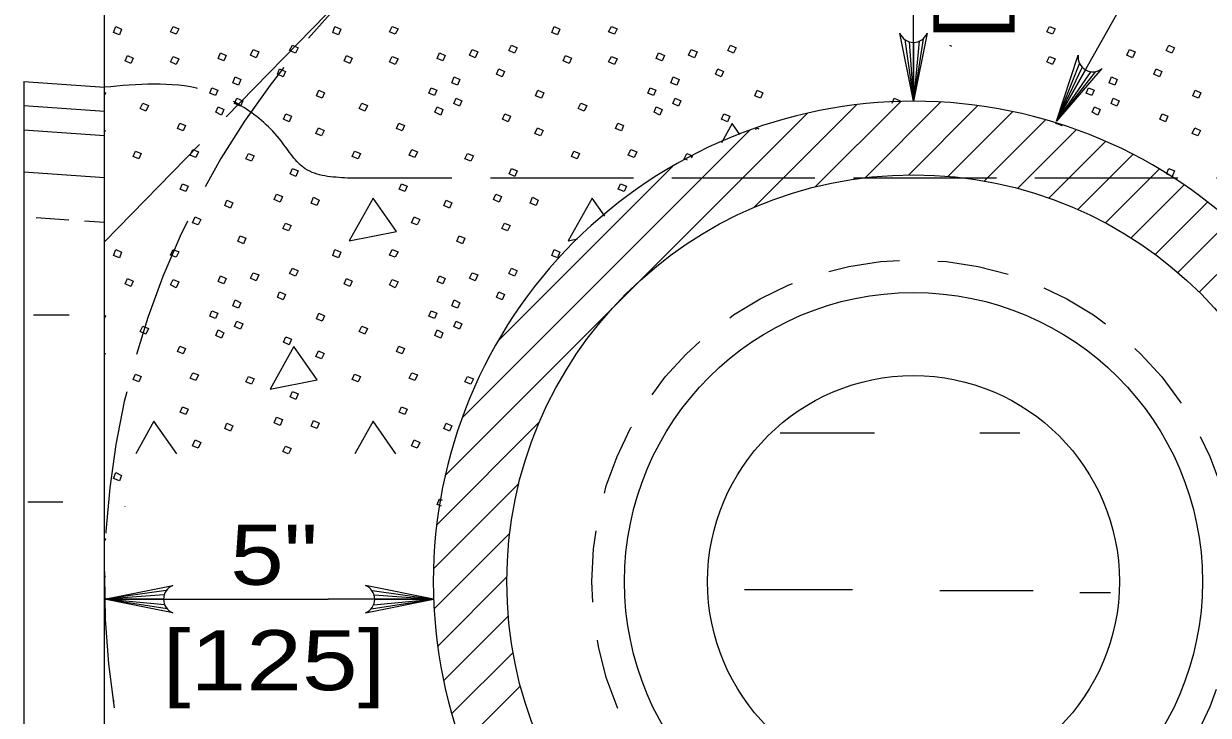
# Model space of a CAD drawing. Extents: x 1036.7 to 1070.7, y 883.9 to 905.9.
# Drawn here: x 1045.517 to 1048.598, y 889.378 to 891.176 of the extents above; entities that cross this region are included whole.
import ezdxf
from ezdxf.enums import TextEntityAlignment as Align

# ---------------------------------------------------------------- set-up
doc = ezdxf.new("R2010")
doc.units = 0
doc.header["$LTSCALE"] = 0.062
doc.linetypes.add('LONG_DASHED', pattern=[7.5, 6, -1.5])
doc.linetypes.add('MEDIUM_DASHED', pattern=[4.5, 3, -1.5])
doc.layers.add('1', color=7, linetype='Continuous', lineweight=13)

msp = doc.modelspace()

# ---------------------------------------------------------------- linework, layer by layer
at = {"layer": '1', "linetype": 'LONG_DASHED', "lineweight": 25}
for p, q in [((1046.96408, 891.87417), (1045.72733, 890.60908)), ((1049.935, 890.77442), (1046.35942, 890.77442))]:
    msp.add_line(p, q, dxfattribs=at)
at = {"layer": '1'}
for p, q in [((1047.83117, 890.974), (1047.83117, 891.574)), ((1047.80875, 891.13425), (1047.83117, 890.97408)), ((1047.81983, 891.12883), (1047.83117, 890.97408)), ((1047.856, 891.13617), (1047.83117, 890.97408)), ((1047.84558, 891.13008), (1047.83117, 890.97408)), ((1047.83117, 891.12725), (1047.83117, 890.97408)), ((1047.92508, 891.12008), (1047.93042, 891.11758)), ((1048.26267, 891.07283), (1048.20325, 890.92225)), ((1048.26967, 891.06258), (1048.20325, 890.92225)), ((1048.27867, 891.05558), (1048.20325, 890.92225)), ((1048.30467, 891.05117), (1048.20325, 890.92225)), ((1048.29258, 891.051), (1048.20325, 890.92225)), ((1047.77533, 890.96875), (1047.78117, 890.98217)), ((1045.51733, 890.96283), (1045.72733, 890.94825)), ((1047.41617, 890.69792), (1047.68275, 890.96458)), ((1047.57567, 890.7515), (1047.79708, 890.97283)), ((1047.7055, 890.77533), (1047.90183, 890.97158)), ((1047.81883, 890.78275), (1047.99875, 890.96267)), ((1047.92125, 890.779), (1048.08933, 890.94708)), ((1046.61425, 890.00217), (1047.55467, 890.94258)), ((1047.35933, 890.91625), (1047.3315, 890.86633)), ((1047.37917, 890.888), (1047.35933, 890.91625)), ((1048.01492, 890.76675), (1048.17417, 890.926)), ((1048.201, 890.91517), (1048.20192, 890.91725)), ((1045.51733, 890.89967), (1045.72733, 890.88508)), ((1046.6585, 890.15242), (1047.40525, 890.89908)), ((1047.421, 890.90033), (1047.42333, 890.90525)), ((1047.42333, 890.90525), (1047.42892, 890.90267)), ((1048.10183, 890.74758), (1048.25442, 890.90017)), ((1048.18292, 890.72258), (1048.33017, 890.86983)), ((1048.25883, 890.6925), (1048.40192, 890.83558)), ((1045.51733, 890.79033), (1045.72733, 890.77575)), ((1046.75042, 890.35033), (1047.20492, 890.80483)), ((1048.33008, 890.65783), (1048.47, 890.79767)), ((1048.39708, 890.61875), (1048.53458, 890.75625)), ((1047.0285, 890.67533), (1046.9955, 890.72233)), ((1048.45992, 890.57558), (1048.59592, 890.71158)), ((1045.55008, 890.67217), (1045.63483, 890.66625)), ((1045.67583, 890.66342), (1045.72733, 890.65983)), ((1048.519, 890.52867), (1048.65408, 890.66375)), ((1048.57417, 890.47783), (1048.709, 890.61267)), ((1045.543, 890.4185), (1045.63542, 890.4185)), ((1045.85608, 890.14267), (1045.80875, 890.058)), ((1045.91542, 890.058), (1045.85608, 890.14267)), ((1046.42575, 890.14267), (1046.3785, 890.058)), ((1046.48517, 890.058), (1046.42575, 890.14267)), ((1046.59133, 889.87333), (1046.85858, 890.1405)), ((1047.4845, 890.112), (1047.72983, 890.112)), ((1048.00383, 890.112), (1048.10775, 890.112)), ((1046.58317, 889.75917), (1046.805, 889.98092)), ((1045.52825, 889.93275), (1045.61892, 889.93275)), ((1046.59867, 889.94083), (1046.60567, 889.93758)), ((1046.58483, 889.65483), (1046.78117, 889.85117)), ((1046.59392, 889.55783), (1046.77375, 889.73767)), ((1045.88808, 889.70225), (1045.72783, 889.67983)), ((1045.88267, 889.69117), (1045.72783, 889.67983)), ((1046.42308, 889.70217), (1046.58333, 889.67975)), ((1046.4285, 889.69108), (1046.58333, 889.67975)), ((1047.39208, 889.70467), (1047.67267, 889.70467)), ((1047.8995, 889.70233), (1048.14267, 889.70233)), ((1048.26342, 889.69758), (1048.34383, 889.69758)), ((1045.881, 889.67983), (1045.72783, 889.67983)), ((1045.88383, 889.66542), (1045.72783, 889.67983)), ((1045.89, 889.655), (1045.72783, 889.67983)), ((1045.72783, 889.67975), (1046.30875, 889.67975)), ((1046.58333, 889.67975), (1046.30875, 889.67975)), ((1046.42117, 889.655), (1046.58333, 889.67975)), ((1046.42733, 889.66542), (1046.58333, 889.67975)), ((1046.43017, 889.67975), (1046.58333, 889.67975)), ((1046.60942, 889.46733), (1046.7775, 889.63542)), ((1046.6305, 889.38242), (1046.78975, 889.54167)), ((1046.65633, 889.30225), (1046.80892, 889.45483))]:
    msp.add_line(p, q, dxfattribs=at)
at = {"layer": '1', "lineweight": 25}
for q in [(1045.51733, 888.41958), (1045.72733, 891.01042)]:
    msp.add_line((1045.51733, 891.025), q, dxfattribs=at)
at = {"layer": '1'}
for points in [[(1048.20325, 890.92225), (1048.94275, 892.23433), (1049.18883, 892.23433)], [(1047.86658, 891.15108), (1047.83117, 890.97408), (1047.79583, 891.15108)], [(1048.32125, 891.05892), (1048.20325, 890.92225), (1048.25958, 891.09375)], [(1045.72733, 890.99742), (1045.73008, 890.99617), (1045.72733, 890.98975)], [(1047.78117, 890.98217), (1047.79617, 890.97517), (1047.79417, 890.9705)], [(1048.20192, 890.91725), (1048.21692, 890.91125), (1048.21608, 890.90933)], [(1045.72733, 890.89908), (1045.72908, 890.89825), (1045.72733, 890.89475)], [(1047.24333, 890.82075), (1047.23442, 890.82433), (1047.24142, 890.83825)], [(1047.24142, 890.83825), (1047.25642, 890.83225), (1047.25317, 890.82575)], [(1046.9955, 890.72233), (1046.93358, 890.61142), (1046.95783, 890.61617)], [(1045.72733, 890.41775), (1045.73008, 890.4165), (1045.72733, 890.41008)], [(1045.72733, 890.31942), (1045.72908, 890.31858), (1045.72733, 890.31508)], [(1046.20517, 890.058), (1046.19092, 890.06375), (1046.19792, 890.07775)], [(1046.19792, 890.07775), (1046.21292, 890.07175), (1046.206, 890.058)], [(1046.60342, 889.9215), (1046.59267, 889.92583), (1046.59867, 889.94083)], [(1045.78142, 889.91967), (1045.78108, 889.91983), (1045.78142, 889.92058)], [(1045.72733, 889.83808), (1045.73008, 889.83683), (1045.72733, 889.83042)], [(1045.72733, 889.73975), (1045.72908, 889.73892), (1045.72733, 889.73542)], [(1045.90483, 889.64442), (1045.72783, 889.67983), (1045.90483, 889.71517)], [(1046.40633, 889.64442), (1046.58333, 889.67975), (1046.40633, 889.71517)], [(1045.75258, 889.4135), (1045.75108, 889.41408), (1045.75258, 889.41783)]]:
    msp.add_lwpolyline(points, dxfattribs=at)
at = {"layer": '1', "lineweight": 25}
msp.add_lwpolyline([(1047.83117, 887.57667), (1045.72733, 887.57667), (1045.72733, 891.87417)], dxfattribs=at)
at = {"layer": '1'}
for points in [[(1045.75708, 891.16808), (1045.77208, 891.16108), (1045.76608, 891.14708), (1045.75108, 891.15308)], [(1045.906, 891.16808), (1045.921, 891.16208), (1045.914, 891.14808), (1045.899, 891.15408)], [(1046.32683, 891.16808), (1046.34183, 891.16108), (1046.33583, 891.14708), (1046.32083, 891.15308)], [(1046.47575, 891.16808), (1046.49075, 891.16208), (1046.48375, 891.14808), (1046.46875, 891.15408)], [(1046.89658, 891.16808), (1046.91158, 891.16108), (1046.90558, 891.14708), (1046.89058, 891.15308)], [(1047.0455, 891.16808), (1047.0605, 891.16208), (1047.0535, 891.14808), (1047.0385, 891.15408)], [(1048.18492, 891.16808), (1048.19992, 891.16208), (1048.19292, 891.14808), (1048.17792, 891.15408)], [(1046.029, 891.10017), (1046.044, 891.09317), (1046.038, 891.07917), (1046.023, 891.08517)], [(1046.11392, 891.10817), (1046.12892, 891.10217), (1046.12192, 891.08717), (1046.10692, 891.09417)], [(1046.21592, 891.12008), (1046.23083, 891.11308), (1046.22392, 891.09917), (1046.20892, 891.10617)], [(1046.59867, 891.10017), (1046.61367, 891.09317), (1046.60767, 891.07917), (1046.59267, 891.08517)], [(1046.68367, 891.10817), (1046.69867, 891.10217), (1046.69167, 891.08717), (1046.67667, 891.09417)], [(1046.78558, 891.12008), (1046.80058, 891.11308), (1046.79358, 891.09917), (1046.77858, 891.10617)], [(1047.16842, 891.10017), (1047.18342, 891.09317), (1047.17742, 891.07917), (1047.16242, 891.08517)], [(1047.25342, 891.10817), (1047.26842, 891.10217), (1047.26142, 891.08717), (1047.24642, 891.09417)], [(1047.35533, 891.12008), (1047.37033, 891.11308), (1047.36333, 891.09917), (1047.34833, 891.10617)], [(1048.39283, 891.10817), (1048.40783, 891.10217), (1048.40083, 891.08717), (1048.38583, 891.09417)], [(1048.49483, 891.12008), (1048.50983, 891.11308), (1048.50283, 891.09917), (1048.48783, 891.10617)], [(1045.78708, 891.09317), (1045.80208, 891.08617), (1045.79608, 891.07217), (1045.78108, 891.07917)], [(1045.906, 891.09017), (1045.921, 891.08417), (1045.914, 891.06917), (1045.899, 891.07617)], [(1046.35683, 891.09317), (1046.37183, 891.08617), (1046.36583, 891.07217), (1046.35083, 891.07917)], [(1046.47575, 891.09017), (1046.49075, 891.08417), (1046.48375, 891.06917), (1046.46875, 891.07617)], [(1046.92658, 891.09317), (1046.9415, 891.08617), (1046.93558, 891.07217), (1046.92058, 891.07917)], [(1047.0455, 891.09017), (1047.0605, 891.08417), (1047.0535, 891.06917), (1047.0385, 891.07617)], [(1048.18492, 891.09017), (1048.19992, 891.08417), (1048.19292, 891.06917), (1048.17792, 891.07617)], [(1046.06692, 891.03717), (1046.08192, 891.03017), (1046.07592, 891.01617), (1046.06092, 891.02217)], [(1046.18292, 891.05817), (1046.19792, 891.05117), (1046.19192, 891.03717), (1046.17692, 891.04417)], [(1046.63667, 891.03717), (1046.65167, 891.03017), (1046.64567, 891.01617), (1046.63067, 891.02217)], [(1046.75267, 891.05817), (1046.76758, 891.05117), (1046.76158, 891.03717), (1046.74667, 891.04417)], [(1047.20642, 891.03717), (1047.22142, 891.03017), (1047.21542, 891.01617), (1047.20042, 891.02217)], [(1047.32233, 891.05817), (1047.33733, 891.05117), (1047.33133, 891.03717), (1047.31633, 891.04417)], [(1048.34592, 891.03717), (1048.36083, 891.03017), (1048.35483, 891.01617), (1048.33992, 891.02217)], [(1048.46183, 891.05817), (1048.47683, 891.05117), (1048.47083, 891.03717), (1048.45583, 891.04417)], [(1046.007, 891.00917), (1046.022, 891.00317), (1046.016, 890.98917), (1046.001, 890.99517)], [(1046.57675, 891.00917), (1046.59167, 891.00317), (1046.58567, 890.98917), (1046.57075, 890.99517)], [(1047.14642, 891.00917), (1047.16142, 891.00317), (1047.15542, 890.98917), (1047.14042, 890.99517)], [(1048.28592, 891.00917), (1048.30092, 891.00317), (1048.29492, 890.98917), (1048.27992, 890.99517)], [(1046.07192, 890.98217), (1046.08692, 890.97517), (1046.08092, 890.96125), (1046.06592, 890.96825)], [(1046.28483, 891.00317), (1046.29983, 890.99617), (1046.29383, 890.98217), (1046.27883, 890.98817)], [(1046.64167, 890.98217), (1046.65667, 890.97517), (1046.65067, 890.96125), (1046.63567, 890.96825)], [(1046.85458, 891.00317), (1046.86958, 890.99617), (1046.86358, 890.98217), (1046.84858, 890.98817)], [(1047.21142, 890.98217), (1047.22642, 890.97517), (1047.22042, 890.96125), (1047.20542, 890.96825)], [(1047.42433, 891.00317), (1047.43933, 890.99617), (1047.43333, 890.98217), (1047.41833, 890.98817)], [(1048.35083, 890.98217), (1048.36583, 890.97517), (1048.35983, 890.96125), (1048.34492, 890.96825)], [(1048.56375, 891.00317), (1048.57875, 890.99617), (1048.57275, 890.98217), (1048.55775, 890.98817)], [(1045.82708, 890.96917), (1045.84208, 890.96325), (1045.83508, 890.94825), (1045.82008, 890.95525)], [(1046.023, 890.95925), (1046.038, 890.95225), (1046.032, 890.93825), (1046.017, 890.94525)], [(1046.39683, 890.96917), (1046.41175, 890.96325), (1046.40475, 890.94825), (1046.38983, 890.95525)], [(1046.59267, 890.95925), (1046.60767, 890.95225), (1046.60167, 890.93825), (1046.58667, 890.94525)], [(1046.9665, 890.96917), (1046.9815, 890.96325), (1046.9745, 890.94825), (1046.9595, 890.95525)], [(1047.16242, 890.95925), (1047.17742, 890.95225), (1047.17142, 890.93825), (1047.15642, 890.94525)], [(1048.30192, 890.95925), (1048.31692, 890.95225), (1048.31092, 890.93825), (1048.29592, 890.94525)], [(1045.923, 890.91725), (1045.938, 890.91125), (1045.932, 890.89725), (1045.917, 890.90325)], [(1046.19892, 890.94125), (1046.21392, 890.93525), (1046.20792, 890.92025), (1046.19292, 890.92725)], [(1046.49275, 890.91725), (1046.50775, 890.91125), (1046.50175, 890.89725), (1046.48675, 890.90325)], [(1046.76858, 890.94125), (1046.78358, 890.93525), (1046.77758, 890.92025), (1046.76258, 890.92725)], [(1047.0625, 890.91725), (1047.0775, 890.91125), (1047.0715, 890.89725), (1047.0565, 890.90325)], [(1047.33833, 890.94125), (1047.35333, 890.93525), (1047.34733, 890.92025), (1047.33233, 890.92725)], [(1048.47783, 890.94125), (1048.49283, 890.93525), (1048.48683, 890.92025), (1048.47183, 890.92725)], [(1046.28383, 890.90525), (1046.29883, 890.89825), (1046.29183, 890.88425), (1046.27683, 890.89025)], [(1046.85358, 890.90525), (1046.86858, 890.89825), (1046.86158, 890.88425), (1046.84658, 890.89025)], [(1048.56275, 890.90525), (1048.57775, 890.89825), (1048.57075, 890.88425), (1048.55575, 890.89025)], [(1045.80808, 890.84425), (1045.82308, 890.83825), (1045.81708, 890.82433), (1045.80208, 890.83025)], [(1045.957, 890.84825), (1045.972, 890.84225), (1045.965, 890.82825), (1045.95, 890.83425)], [(1046.10192, 890.83825), (1046.11692, 890.83225), (1046.10992, 890.81833), (1046.09492, 890.82433)], [(1046.37783, 890.84425), (1046.39283, 890.83825), (1046.38683, 890.82433), (1046.37183, 890.83025)], [(1046.52675, 890.84825), (1046.54175, 890.84225), (1046.53475, 890.82825), (1046.51975, 890.83425)], [(1046.67167, 890.83825), (1046.68667, 890.83225), (1046.67967, 890.81833), (1046.66467, 890.82433)], [(1046.9475, 890.84425), (1046.9625, 890.83825), (1046.9565, 890.82433), (1046.9415, 890.83025)], [(1047.0965, 890.84825), (1047.1115, 890.84225), (1047.1045, 890.82825), (1047.0895, 890.83425)], [(1046.21592, 890.79933), (1046.23083, 890.79333), (1046.22492, 890.77833), (1046.20992, 890.78533)], [(1046.78558, 890.79933), (1046.80058, 890.79333), (1046.79458, 890.77833), (1046.77958, 890.78533)], [(1048.49483, 890.79933), (1048.50983, 890.79333), (1048.50383, 890.77833), (1048.48883, 890.78533)], [(1045.93, 890.75933), (1045.945, 890.75333), (1045.939, 890.73933), (1045.924, 890.74533)], [(1046.49975, 890.75933), (1046.51475, 890.75333), (1046.50875, 890.73933), (1046.49375, 890.74533)], [(1047.0695, 890.75933), (1047.0845, 890.75333), (1047.0785, 890.73933), (1047.0635, 890.74533)], [(1046.17492, 890.73233), (1046.18992, 890.72633), (1046.18392, 890.71133), (1046.16892, 890.71833)], [(1046.74467, 890.73233), (1046.75958, 890.72633), (1046.75367, 890.71133), (1046.73867, 890.71833)], [(1046.046, 890.71733), (1046.06092, 890.71033), (1046.05492, 890.69633), (1046.04, 890.70333)], [(1046.27083, 890.72433), (1046.28583, 890.71733), (1046.27983, 890.70333), (1046.26483, 890.70933)], [(1046.42575, 890.72233), (1046.36383, 890.61142), (1046.48675, 890.63542)], [(1046.61567, 890.71733), (1046.63067, 890.71033), (1046.62467, 890.69633), (1046.60967, 890.70333)], [(1046.84058, 890.72433), (1046.85558, 890.71733), (1046.84958, 890.70333), (1046.83458, 890.70933)], [(1045.963, 890.67342), (1045.978, 890.66642), (1045.971, 890.65242), (1045.956, 890.65842)], [(1046.53275, 890.67342), (1046.54775, 890.66642), (1046.54075, 890.65242), (1046.52575, 890.65842)], [(1046.19792, 890.65742), (1046.21292, 890.65142), (1046.20592, 890.63742), (1046.19092, 890.64342)], [(1046.76758, 890.65742), (1046.78258, 890.65142), (1046.77558, 890.63742), (1046.76058, 890.64342)], [(1046.07992, 890.62442), (1046.09492, 890.61842), (1046.08892, 890.60342), (1046.07392, 890.61042)], [(1046.64967, 890.62442), (1046.66467, 890.61842), (1046.65867, 890.60342), (1046.64367, 890.61042)], [(1045.75708, 890.58842), (1045.77208, 890.58142), (1045.76608, 890.56742), (1045.75108, 890.57342)], [(1045.906, 890.58842), (1045.921, 890.58242), (1045.914, 890.56842), (1045.899, 890.57442)], [(1046.32683, 890.58842), (1046.34183, 890.58142), (1046.33583, 890.56742), (1046.32083, 890.57342)], [(1046.47575, 890.58842), (1046.49075, 890.58242), (1046.48375, 890.56842), (1046.46875, 890.57442)], [(1046.89658, 890.58842), (1046.91158, 890.58142), (1046.90558, 890.56742), (1046.89058, 890.57342)], [(1045.78708, 890.5135), (1045.80208, 890.5065), (1045.79608, 890.4925), (1045.78108, 890.4995)], [(1046.029, 890.5205), (1046.044, 890.5135), (1046.038, 890.4995), (1046.023, 890.5055)], [(1046.11392, 890.5285), (1046.12892, 890.5225), (1046.12192, 890.5075), (1046.10692, 890.5145)], [(1046.21592, 890.54042), (1046.23083, 890.5335), (1046.22392, 890.5195), (1046.20892, 890.5265)], [(1046.35683, 890.5135), (1046.37183, 890.5065), (1046.36583, 890.4925), (1046.35083, 890.4995)], [(1046.59867, 890.5205), (1046.61367, 890.5135), (1046.60767, 890.4995), (1046.59267, 890.5055)], [(1046.68367, 890.5285), (1046.69867, 890.5225), (1046.69167, 890.5075), (1046.67667, 890.5145)], [(1046.78558, 890.54042), (1046.80058, 890.5335), (1046.79358, 890.5195), (1046.77858, 890.5265)], [(1045.906, 890.5105), (1045.921, 890.5045), (1045.914, 890.4895), (1045.899, 890.4965)], [(1046.47575, 890.5105), (1046.49075, 890.5045), (1046.48375, 890.4895), (1046.46875, 890.4965)], [(1046.06692, 890.4575), (1046.08192, 890.4505), (1046.07592, 890.4365), (1046.06092, 890.4425)], [(1046.18292, 890.4785), (1046.19792, 890.4715), (1046.19192, 890.4575), (1046.17692, 890.4645)], [(1046.63667, 890.4575), (1046.65167, 890.4505), (1046.64567, 890.4365), (1046.63067, 890.4425)], [(1046.75267, 890.4785), (1046.76758, 890.4715), (1046.76158, 890.4575), (1046.74667, 890.4645)], [(1046.007, 890.4295), (1046.022, 890.4235), (1046.016, 890.4095), (1046.001, 890.4155)], [(1046.28483, 890.4235), (1046.29983, 890.4165), (1046.29383, 890.4025), (1046.27883, 890.4085)], [(1046.57675, 890.4295), (1046.59167, 890.4235), (1046.58567, 890.4095), (1046.57075, 890.4155)], [(1045.82708, 890.3895), (1045.84208, 890.38358), (1045.83508, 890.36858), (1045.82008, 890.37558)], [(1046.07192, 890.4025), (1046.08692, 890.3955), (1046.08092, 890.38158), (1046.06592, 890.38858)], [(1046.39683, 890.3895), (1046.41175, 890.38358), (1046.40475, 890.36858), (1046.38983, 890.37558)], [(1046.64167, 890.4025), (1046.65667, 890.3955), (1046.65067, 890.38158), (1046.63567, 890.38858)], [(1046.023, 890.37958), (1046.038, 890.37258), (1046.032, 890.35858), (1046.017, 890.36558)], [(1046.19892, 890.36158), (1046.21392, 890.35558), (1046.20792, 890.34058), (1046.19292, 890.34758)], [(1046.59267, 890.37958), (1046.60767, 890.37258), (1046.60167, 890.35858), (1046.58667, 890.36558)], [(1045.923, 890.33758), (1045.938, 890.33158), (1045.932, 890.31758), (1045.917, 890.32358)], [(1046.21992, 890.33658), (1046.15792, 890.22567), (1046.28083, 890.24958)], [(1046.49275, 890.33758), (1046.50775, 890.33158), (1046.50175, 890.31758), (1046.48675, 890.32358)], [(1046.28383, 890.32558), (1046.29883, 890.31858), (1046.29183, 890.30458), (1046.27683, 890.31058)], [(1045.957, 890.26858), (1045.972, 890.26258), (1045.965, 890.24867), (1045.95, 890.25458)], [(1046.52675, 890.26858), (1046.54175, 890.26258), (1046.53475, 890.24867), (1046.51975, 890.25458)], [(1045.80808, 890.26458), (1045.82308, 890.25858), (1045.81708, 890.24467), (1045.80208, 890.25058)], [(1046.10192, 890.25858), (1046.11692, 890.25258), (1046.10992, 890.23867), (1046.09492, 890.24467)], [(1046.37783, 890.26458), (1046.39283, 890.25858), (1046.38683, 890.24467), (1046.37183, 890.25058)], [(1046.67167, 890.25858), (1046.68667, 890.25258), (1046.67967, 890.23867), (1046.66467, 890.24467)], [(1046.21592, 890.21967), (1046.23083, 890.21367), (1046.22492, 890.19867), (1046.20992, 890.20567)], [(1045.93, 890.17967), (1045.945, 890.17367), (1045.939, 890.15967), (1045.924, 890.16567)], [(1046.49975, 890.17967), (1046.51475, 890.17367), (1046.50875, 890.15967), (1046.49375, 890.16567)], [(1046.17492, 890.15267), (1046.18992, 890.14667), (1046.18392, 890.13167), (1046.16892, 890.13867)], [(1046.27083, 890.14467), (1046.28583, 890.13767), (1046.27983, 890.12367), (1046.26483, 890.12967)], [(1046.046, 890.13767), (1046.06092, 890.13067), (1046.05492, 890.11667), (1046.04, 890.12367)], [(1046.61567, 890.13767), (1046.63067, 890.13067), (1046.62467, 890.11667), (1046.60967, 890.12367)], [(1045.963, 890.09375), (1045.978, 890.08675), (1045.971, 890.07275), (1045.956, 890.07875)], [(1046.53275, 890.09375), (1046.54775, 890.08675), (1046.54075, 890.07275), (1046.52575, 890.07875)], [(1045.75708, 890.00875), (1045.77208, 890.00175), (1045.76608, 889.98775), (1045.75108, 889.99375)]]:
    msp.add_lwpolyline(points, close=True, dxfattribs=at)
for centre, start, end in [((1047.83116, 891.16534), 202.08782, 337.91395), ((1048.29741, 891.0888), 172.59856, 308.42469), ((1045.91914, 889.67984), 112.08782, 247.91395), ((1046.392, 889.67983), 292.08605, 67.91218)]:
    msp.add_arc(centre, 0.0382, start, end, dxfattribs=at)
at = {"layer": '1', "linetype": 'LONG_DASHED', "lineweight": 25}
for centre, major_axis, start_param, end_param in [((1047.87683, 889.72543), (-2.14947, 0), 4.7336189, 6.4365345), ((1047.78549, 889.72543), (2.14947, 0), 4.7336585, 7.8327121)]:
    msp.add_ellipse(centre, major_axis=major_axis, ratio=0.999895, start_param=start_param, end_param=end_param, dxfattribs=at)
at = {"layer": '1', "lineweight": 25}
for start_param, end_param in [(1.5707963, 3.1415927), (4.712389, 7.8539816), (3.1415927, 4.712389)]:
    msp.add_ellipse((1047.8312, 889.72543), major_axis=(1.24875, 0), ratio=0.999895, start_param=start_param, end_param=end_param, dxfattribs=at)
for major_axis in [(1.05751, 0), (0.75159, 0), (0.53563, 0)]:
    msp.add_ellipse((1047.8312, 889.72543), major_axis=major_axis, ratio=0.999895, dxfattribs=at)
at = {"layer": '1', "linetype": 'MEDIUM_DASHED'}
msp.add_ellipse((1047.8312, 889.72543), major_axis=(0.83646, 0), ratio=0.999895, dxfattribs=at)
at = {"layer": '1', "linetype": 'LONG_DASHED', "lineweight": 25}
msp.add_spline([(1046.35942, 890.77442), (1046.24967, 890.7985), (1046.18675, 890.87075), (1046.09017, 890.95742), (1045.98167, 891.00458), (1045.72733, 891.01042)], degree=3, dxfattribs=at)

# ---------------------------------------------------------------- texts
at = {"layer": '1', "width": 1.25}
msp.add_text('[125]', height=0.156, rotation=90, dxfattribs=at).set_placement((1048.0475, 891.42467), align=Align.CENTER)
at = {"layer": '1'}
for s, width, p in [('5"', 1.2, (1046.16846, 889.71733)), ('[125]', 1.25, (1046.16842, 889.44333))]:
    msp.add_text(s, height=0.156, dxfattribs=dict(at, width=width)).set_placement(p, align=Align.CENTER)

doc.saveas('drawing.dxf')
